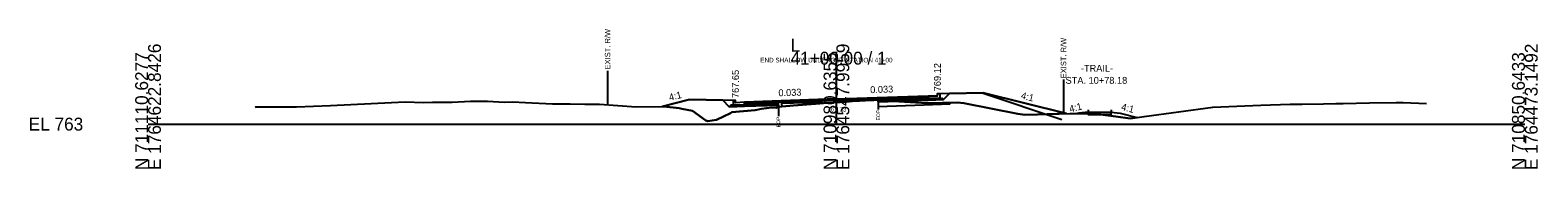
# Model space of a CAD drawing. Extents: x -26 to 5303, y -10 to 9578.
# Drawn here: x 2974.3 to 3302.8, y 990.3 to 1020.4 of the extents above; entities that cross this region are included whole.
import ezdxf

# ---------------------------------------------------------------- set-up
doc = ezdxf.new("R2010")
doc.units = 0
for name, color, linetype in [('Default', 7, 'Continuous'), ('Exist CMT Pavement', 7, 'Continuous'), ('Exist Cross Section Cell', 7, 'Continuous'), ('Exist XS Ground Line', 7, 'Continuous'), ('Old_Level_10', 7, 'Continuous'), ('Old_Level_3', 7, 'Continuous'), ('Old_Level_4', 7, 'Continuous'), ('Prop CMT Conc Surface', 7, 'Continuous'), ('Prop CMT Concrete Structures', 7, 'Continuous'), ('Prop CMT Pvmt Course 1', 7, 'Continuous'), ('Prop CMT Pvmt Course 1 CG', 7, 'Continuous'), ('Prop CMT Pvmt Course 2', 7, 'Continuous'), ('Prop CMT Pvmt Course 3', 7, 'Continuous'), ('Prop CMT Pvmt Surface', 7, 'Continuous'), ('Prop CMT Slope Grass', 7, 'Continuous'), ('Prop CMT Subgrade Earthwork', 7, 'Continuous'), ('Prop Shade Light', 7, 'Continuous'), ('Prop XS Earthwork Shape', 7, 'Continuous'), ('Prop XS EOT Tick Mark', 7, 'Continuous'), ('Prop XS Hydro Elevations', 7, 'Continuous'), ('Prop XS Hydro Slope Text', 7, 'Continuous'), ('Prop XS SE Text', 7, 'Continuous'), ('Prop XS Side Slope Text', 7, 'Continuous'), ('Prop XS Wedging', 7, 'Continuous')]:
    doc.layers.add(name, color=color, linetype=linetype)

msp = doc.modelspace()

# ---------------------------------------------------------------- linework, layer by layer
at = {"layer": 'Exist CMT Pavement'}
msp.add_lwpolyline([(3137.34, 1003.74), (3138.08, 1003.82), (3139.84, 1003.98), (3140.64, 1004.04), (3143.58, 1004.29), (3146.41, 1004.51), (3147.15, 1004.57), (3147.93, 1004.63), (3149.29, 1004.7), (3150, 1004.74), (3150.38, 1004.77), (3152.18, 1004.87), (3153.5, 1004.97), (3154.49, 1005.03), (3155.06, 1005.07), (3157.18, 1005.18), (3158.12, 1005.23), (3159.12, 1005.24)], dxfattribs=at)
at = {"layer": 'Exist Cross Section Cell'}
for p, q in [((3150, 1000), (3150, 1015.72)), ((3000, 1000), (3150, 1000)), ((3150, 1000), (3300, 1000))]:
    msp.add_line(p, q, dxfattribs=at)
at = {"layer": 'Exist XS Ground Line'}
msp.add_lwpolyline([(3023.32, 1003.7), (3023.48, 1003.75), (3024.02, 1003.75), (3032.38, 1003.75), (3039.75, 1004.07), (3053.05, 1004.7), (3056.06, 1004.84), (3060.04, 1004.72), (3062, 1004.77), (3066.24, 1004.8), (3070.27, 1004.95), (3073.99, 1004.97), (3077.64, 1004.79), (3079.39, 1004.86), (3082.28, 1004.69), (3088.12, 1004.4), (3091.95, 1004.38), (3095.16, 1004.3), (3098.35, 1004.3), (3106.39, 1003.73), (3112.36, 1003.86), (3115.76, 1003.44), (3116.31, 1003.34), (3118.64, 1002.91), (3121.57, 1000.79), (3121.98, 1000.64), (3123.86, 1000.95), (3126.9, 1002.38), (3127.21, 1002.57), (3132.31, 1003.06), (3133.68, 1003.32), (3135.84, 1003.61), (3136.88, 1003.53), (3137.34, 1003.74), (3138.08, 1003.82), (3139.84, 1003.98), (3140.64, 1004.04), (3143.52, 1004.28), (3145.34, 1004.42), (3146.41, 1004.51), (3147.15, 1004.57), (3147.93, 1004.63), (3148.53, 1004.66), (3149.29, 1004.7), (3150, 1004.73), (3150.83, 1004.78), (3152.18, 1004.87), (3152.66, 1004.91), (3153.5, 1004.97), (3155.06, 1005.07), (3156.32, 1005.13), (3158.12, 1005.23), (3159.12, 1005.24), (3163.58, 1004.93), (3169.75, 1004.54), (3176.39, 1004.68), (3177.77, 1004.58), (3189.51, 1002.25), (3191.03, 1002.05), (3193.78, 1002.11), (3200.89, 1002.29), (3203.92, 1002.3), (3205.9, 1002.3), (3210.87, 1001.67), (3214.02, 1001.25), (3217.05, 1001.68), (3231.99, 1003.67), (3242.48, 1004.12), (3248.88, 1004.33), (3251.52, 1004.36), (3256.11, 1004.4), (3258.84, 1004.45), (3260.42, 1004.48), (3266.17, 1004.64), (3271.96, 1004.7), (3272.9, 1004.7), (3273.51, 1004.68), (3278.55, 1004.44)], dxfattribs=at)
at = {"layer": 'Old_Level_10'}
for p, q in [((3100.13, 1011.57), (3100.13, 1004.17)), ((3199.48, 1009.66), (3199.48, 1002.26)), ((3137.34, 1003.74), (3137.34, 1001.69)), ((3159.12, 1005.24), (3159.12, 1003.19))]:
    msp.add_line(p, q, dxfattribs=at)
at = {"layer": 'Old_Level_4'}
msp.add_line((3182, 1006.69), (3199.08, 1000.99), dxfattribs=at)
at = {"layer": 'Prop CMT Conc Surface'}
for points in [[(3170, 1006.13), (3172, 1006.12)], [(3172, 1006.12), (3172, 1006.62), (3172.5, 1006.62)], [(3128, 1004.65), (3128, 1005.15), (3127.5, 1005.15)], [(3130, 1004.8), (3128, 1004.65)]]:
    msp.add_lwpolyline(points, dxfattribs=at)
at = {"layer": 'Prop CMT Concrete Structures'}
for points in [[(3170, 1006.13), (3172, 1006.12), (3172, 1006.62), (3172.5, 1006.62)], [(3172.5, 1006.62), (3172.5, 1005.63), (3170, 1005.55)], [(3170, 1005.55), (3170, 1006.13)], [(3130, 1004.8), (3128, 1004.65), (3128, 1005.15), (3127.5, 1005.15)], [(3127.5, 1005.15), (3127.5, 1004.13), (3130, 1004.21)], [(3130, 1004.21), (3130, 1004.8)]]:
    msp.add_lwpolyline(points, dxfattribs=at)
at = {"layer": 'Prop CMT Pvmt Course 1'}
for points in [[(3150, 1005.47), (3130, 1004.8)], [(3150, 1005.47), (3170, 1006.13)], [(3159.12, 1005.52), (3150, 1005.22)], [(3150, 1005.22), (3150, 1005.47)], [(3170, 1005.88), (3159.12, 1005.52)], [(3159.12, 1005.52), (3159.12, 1005.52)], [(3170, 1006.13), (3170, 1005.88)], [(3130, 1004.8), (3130, 1004.55)], [(3130, 1004.55), (3137.34, 1004.79)], [(3137.34, 1004.79), (3150, 1005.22)], [(3137.34, 1004.79), (3137.34, 1004.79)], [(3150, 1005.22), (3150, 1005.22), (3150, 1005.22)]]:
    msp.add_lwpolyline(points, dxfattribs=at)
at = {"layer": 'Prop CMT Pvmt Course 1 CG'}
for points in [[(3170, 1005.55), (3173, 1005.65), (3173.32, 1005.33)], [(3170, 1005.22), (3170, 1005.55)], [(3173.32, 1005.33), (3170, 1005.22)], [(3130, 1004.21), (3127, 1004.11), (3126.66, 1003.77)], [(3126.66, 1003.77), (3130, 1003.88)], [(3130, 1003.88), (3130, 1004.21)]]:
    msp.add_lwpolyline(points, dxfattribs=at)
at = {"layer": 'Prop CMT Pvmt Course 2'}
for points in [[(3159.12, 1005.52), (3170, 1005.88)], [(3170, 1005.55), (3159.12, 1005.19)], [(3159.12, 1005.19), (3159.12, 1005.52)], [(3170, 1005.88), (3170, 1005.55)], [(3137.34, 1004.79), (3130, 1004.55)], [(3130, 1004.55), (3130, 1004.21)], [(3130, 1004.21), (3137.34, 1004.46)], [(3137.34, 1004.46), (3137.34, 1004.79)]]:
    msp.add_lwpolyline(points, dxfattribs=at)
at = {"layer": 'Prop CMT Pvmt Course 3'}
for points in [[(3159.12, 1005.19), (3170, 1005.55)], [(3170, 1005.55), (3170, 1005.22)], [(3137.34, 1004.46), (3130, 1004.21)], [(3130, 1004.21), (3130, 1003.88)], [(3130, 1003.88), (3137.34, 1004.13)], [(3137.34, 1004.13), (3137.34, 1004.46)], [(3170, 1005.22), (3159.12, 1004.85)], [(3159.12, 1004.85), (3159.12, 1005.19)]]:
    msp.add_lwpolyline(points, dxfattribs=at)
at = {"layer": 'Prop CMT Pvmt Surface'}
msp.add_line((3204.82, 1002.58), (3209.84, 1002.58), dxfattribs=at)
for points in [[(3150, 1005.47), (3130, 1004.8)], [(3150, 1005.47), (3170, 1006.13)]]:
    msp.add_lwpolyline(points, dxfattribs=at)
at = {"layer": 'Prop CMT Slope Grass'}
for p, q in [((3202.82, 1002.39), (3204.82, 1002.58)), ((3209.84, 1002.58), (3211.84, 1002.39))]:
    msp.add_line(p, q, dxfattribs=at)
for points in [[(3127.5, 1005.15), (3118, 1005.34), (3112.04, 1003.85)], [(3172.5, 1006.62), (3182, 1006.81), (3200.15, 1002.27)], [(3202.82, 1002.39), (3202.45, 1002.3)], [(3211.84, 1002.39), (3215.54, 1001.46)]]:
    msp.add_lwpolyline(points, dxfattribs=at)
at = {"layer": 'Prop CMT Subgrade Earthwork'}
for p, q in [((3137.34, 1004.13), (3137.34, 1003.74)), ((3159.12, 1005.24), (3159.12, 1004.85)), ((3204.82, 1002.08), (3204.82, 1002.58)), ((3204.82, 1002.08), (3209.84, 1002.08)), ((3209.84, 1002.08), (3209.84, 1002.58))]:
    msp.add_line(p, q, dxfattribs=at)
for points in [[(3170, 1005.22), (3173.32, 1005.33), (3174.66, 1006.66)], [(3130, 1003.88), (3126.66, 1003.77), (3125.23, 1005.19)], [(3137.34, 1004.13), (3130, 1003.88)], [(3159.12, 1004.85), (3170, 1005.22)]]:
    msp.add_lwpolyline(points, dxfattribs=at)
at = {"layer": 'Prop Shade Light'}
for p, q in [((3162.87, 1004.98), (3159.12, 1004.85)), ((3159.12, 1004.85), (3159.12, 1003.85)), ((3174.81, 1004.38), (3174.79, 1004.64))]:
    msp.add_line(p, q, dxfattribs=at)
for points in [[(3159.12, 1003.85), (3169.04, 1004.18), (3174.81, 1004.38)], [(3174.79, 1004.64), (3169.75, 1004.54), (3163.58, 1004.93), (3162.87, 1004.98)], [(3169.04, 1004.18), (3174.81, 1004.38)]]:
    msp.add_lwpolyline(points, dxfattribs=at)
at = {"layer": 'Prop XS Earthwork Shape'}
for points in [[(3118, 1005.34), (3112.04, 1003.85), (3112.36, 1003.86), (3115.76, 1003.44), (3116.31, 1003.34), (3118.64, 1002.91), (3121.57, 1000.79), (3121.98, 1000.64), (3123.86, 1000.95), (3126.9, 1002.38), (3127.21, 1002.57), (3132.31, 1003.06), (3133.68, 1003.32), (3135.84, 1003.61), (3136.88, 1003.53), (3137.34, 1003.74), (3137.34, 1004.13), (3130, 1003.88), (3126.66, 1003.77), (3125.23, 1005.19)], [(3137.34, 1004.13), (3137.34, 1003.74), (3136.88, 1003.53), (3135.84, 1003.61), (3133.68, 1003.32), (3132.31, 1003.06), (3127.21, 1002.57), (3126.9, 1002.38), (3123.86, 1000.95), (3121.98, 1000.64), (3121.57, 1000.79), (3118.64, 1002.91), (3116.31, 1003.34), (3115.76, 1003.44), (3112.36, 1003.86), (3112.04, 1003.85), (3118, 1005.34), (3125.23, 1005.19), (3126.66, 1003.77), (3130, 1003.88)], [(3170, 1005.22), (3173.32, 1005.33), (3174.66, 1006.66), (3182, 1006.81), (3200.15, 1002.27), (3193.78, 1002.11), (3191.03, 1002.05), (3189.51, 1002.25), (3177.77, 1004.58), (3176.39, 1004.68), (3169.75, 1004.54), (3163.58, 1004.93), (3162.87, 1004.98)], [(3163.58, 1004.93), (3169.75, 1004.54), (3176.39, 1004.68), (3177.77, 1004.58), (3189.51, 1002.25), (3191.03, 1002.05), (3193.78, 1002.11), (3200.15, 1002.27), (3182, 1006.81), (3174.66, 1006.66), (3173.32, 1005.33), (3170, 1005.22), (3162.87, 1004.98)], [(3159.12, 1004.85), (3162.87, 1004.98), (3159.12, 1005.24)], [(3159.12, 1005.24), (3159.12, 1004.85), (3162.87, 1004.98)], [(3203.92, 1002.3), (3204.82, 1002.3), (3204.82, 1002.58), (3202.82, 1002.39), (3202.45, 1002.3)], [(3202.82, 1002.39), (3204.82, 1002.58), (3204.82, 1002.3), (3203.92, 1002.3), (3202.45, 1002.3)], [(3204.82, 1002.08), (3204.82, 1002.3), (3205.9, 1002.3), (3207.64, 1002.08)], [(3204.82, 1002.3), (3205.9, 1002.3), (3207.64, 1002.08), (3204.82, 1002.08)], [(3209.84, 1002.08), (3209.84, 1002.58), (3211.84, 1002.39), (3215.54, 1001.46), (3214.02, 1001.25), (3210.87, 1001.67), (3207.64, 1002.08)], [(3211.84, 1002.39), (3215.54, 1001.46), (3214.02, 1001.25), (3210.87, 1001.67), (3207.64, 1002.08), (3209.84, 1002.08), (3209.84, 1002.58)]]:
    msp.add_lwpolyline(points, close=True, dxfattribs=at)
at = {"layer": 'Prop XS EOT Tick Mark'}
for p, q in [((3204.82, 1003.08), (3204.82, 1002.58)), ((3209.84, 1003.08), (3209.84, 1002.58))]:
    msp.add_line(p, q, dxfattribs=at)
at = {"layer": 'Prop XS Wedging'}
for points in [[(3138.08, 1003.82), (3138.08, 1004.88), (3139.84, 1004.93), (3140.64, 1004.95), (3143.58, 1005.04), (3146.41, 1005.12), (3147.15, 1005.14), (3147.93, 1005.16), (3149.29, 1005.2), (3150, 1005.22), (3150.38, 1005.23), (3152.18, 1005.28), (3153.5, 1005.31), (3154.49, 1005.34), (3155.06, 1005.36), (3157.18, 1005.41), (3158.12, 1005.44), (3159.12, 1005.47), (3159.12, 1005.24), (3158.12, 1005.23), (3157.18, 1005.18), (3155.06, 1005.07), (3154.49, 1005.03), (3153.5, 1004.97), (3152.18, 1004.88), (3150.38, 1004.77), (3150, 1004.74), (3149.29, 1004.7), (3147.93, 1004.63), (3147.15, 1004.57), (3146.41, 1004.51), (3143.58, 1004.29), (3140.64, 1004.04), (3139.84, 1003.98)], [(3138.08, 1003.82), (3138.08, 1004.55), (3139.84, 1004.6), (3140.64, 1004.62), (3143.58, 1004.71), (3146.41, 1004.79), (3146.82, 1004.8), (3147.06, 1004.57), (3146.41, 1004.51), (3143.58, 1004.29), (3140.64, 1004.04), (3139.84, 1003.98)]]:
    msp.add_lwpolyline(points, close=True, dxfattribs=at)

# ---------------------------------------------------------------- texts
at = {"layer": 'Default'}
msp.add_text('-', height=0.0001, dxfattribs=at).set_placement((3000, 1000))
at = {"layer": 'Exist Cross Section Cell'}
for s, p in [('L', (3140, 1015.72)), ('41+00.00 / 1', (3140, 1012.92)), ('EL 763', (2974, 998.6))]:
    msp.add_text(s, height=2.8, dxfattribs=at).set_placement(p)
for s, p in [('N 711110.6277', (3000, 990)), ('E 1764622.8426', (3002.8, 990)), ('N 710980.6355', (3150, 990)), ('E 1764547.9959', (3152.8, 990)), ('N 710850.6433', (3300, 990)), ('E 1764473.1492', (3302.8, 990))]:
    msp.add_text(s, height=2.8, rotation=90, dxfattribs=at).set_placement(p)
at = {"layer": 'Old_Level_10'}
for s, height, p in [('EXIST. R/W', 1.181, (3100.72, 1011.88)), ('EXIST. R/W', 1.181, (3200.07, 1009.96)), ('EOP', 0.787, (3159.51, 1000.79)), ('EOP', 0.787, (3137.74, 999.3))]:
    msp.add_text(s, height=height, rotation=90, dxfattribs=at).set_placement(p)
at = {"layer": 'Old_Level_3'}
msp.add_text('767.73', height=1, dxfattribs=at).set_placement((3147.95, 1002.73))
at = {"layer": 'Old_Level_4'}
msp.add_text(' END SHALLOW UNDERCUT STATION 41+00', height=1, dxfattribs=at).set_placement((3133.02, 1013.4))
at = {"layer": 'Prop XS Hydro Elevations'}
for s, p in [('769.12', (3172.75, 1007.12)), ('767.65', (3128.75, 1005.65))]:
    msp.add_text(s, height=1.5, rotation=90, dxfattribs=at).set_placement(p)
at = {"layer": 'Prop XS Hydro Slope Text'}
for s, p in [('-TRAIL-', (3203.27, 1011.37)), ('STA. 10+78.18', (3199.93, 1008.75))]:
    msp.add_text(s, height=1.5, dxfattribs=at).set_placement(p)
at = {"layer": 'Prop XS SE Text'}
for p in [(3137.38, 1006.04), (3157.38, 1006.71)]:
    msp.add_text('0.033', height=1.5, rotation=1.9153, dxfattribs=at).set_placement(p)
at = {"layer": 'Prop XS Side Slope Text'}
for rotation, p in [(14.0362, (3113.69, 1005.03)), (345.9638, (3190.1, 1005.56)), (14.0362, (3200.93, 1002.53)), (345.9638, (3211.94, 1003.09))]:
    msp.add_text('4:1', height=1.5, rotation=rotation, dxfattribs=at).set_placement(p)

doc.saveas('drawing.dxf')
